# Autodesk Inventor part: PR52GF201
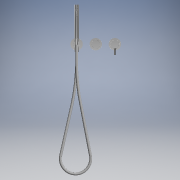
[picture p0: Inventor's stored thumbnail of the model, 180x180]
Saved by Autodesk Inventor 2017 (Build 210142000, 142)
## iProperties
Created: 2022-01
Part Number: PR52GF201
Material: Generico
Document SubType Name: Modeling
Designer: PIZZERA
Density: 1 g/cm^3
Appearance: Default
Author: PIZZERA
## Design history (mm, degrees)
feature "Base3"
node "Solido1"
node "Solido4"
